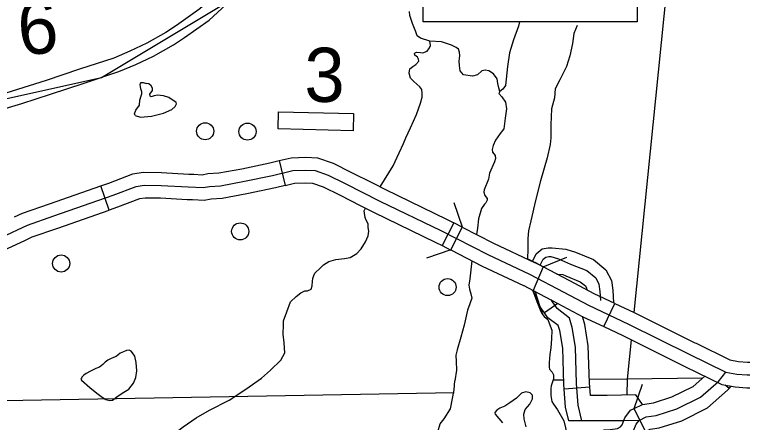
# Model space of a CAD drawing. Extents: x 22866 to 28196, y 1324810 to 1328105.
# Drawn here: x 25255.5 to 25357.6, y 1326025 to 1326082.2 of the extents above; entities that cross this region are included whole.
import ezdxf

# ---------------------------------------------------------------- set-up
doc = ezdxf.new("R2010")
doc.units = 0
for name, color, linetype in [('Default', 7, 'Continuous'), ('Level 19', 7, 'Continuous'), ('Level 31', 7, 'Continuous'), ('Level 32', 7, 'Continuous'), ('Level 35', 7, 'Continuous'), ('Level 38', 7, 'Continuous'), ('Level 4', 7, 'Continuous'), ('Level 46', 7, 'Continuous'), ('Level 5', 7, 'Continuous'), ('Level 56', 7, 'Continuous'), ('Level 9', 7, 'Continuous')]:
    doc.layers.add(name, color=color, linetype=linetype)

msp = doc.modelspace()

# ---------------------------------------------------------------- linework, layer by layer
at = {"layer": 'Default'}
for p, q in [((25267.72, 1326073.42), (25286.19, 1326084.53)), ((25247.38, 1326068.88), (25267.72, 1326073.42))]:
    msp.add_line(p, q, dxfattribs=at)
msp.add_lwpolyline([(25312.85, 1326111.22), (25342.85, 1326111.22), (25342.85, 1326081.22), (25312.85, 1326081.22)], close=True, dxfattribs=at)
msp.add_lwpolyline([(25312.85, 1326111.22), (25342.85, 1326111.22), (25342.85, 1326081.22), (25312.85, 1326081.22)], close=True, dxfattribs=at)
at = {"layer": 'Level 19'}
for points in [[(25294.2, 1326097.43), (25292, 1326094.49), (25288.16, 1326089.69), (25287.08, 1326088.34), (25285.72, 1326086.86), (25283.85, 1326085.15), (25281.53, 1326083.06), (25278.23, 1326080.71), (25276.73, 1326079.74), (25274.1, 1326078.22), (25271.69, 1326077.1), (25269.43, 1326076.14), (25264.65, 1326074.56), (25259.94, 1326073), (25255.94, 1326071.72), (25252.61, 1326070.71), (25248.87, 1326069.47), (25245.88, 1326068.29), (25242.81, 1326066.99), (25239.52, 1326065.45), (25236.93, 1326064.23)], [(25237.8, 1326062.38), (25240.39, 1326063.6), (25243.64, 1326065.12), (25246.65, 1326066.4), (25249.57, 1326067.55), (25253.23, 1326068.77), (25256.54, 1326069.77), (25260.58, 1326071.06), (25265.29, 1326072.62), (25270.15, 1326074.23), (25272.53, 1326075.24), (25275.04, 1326076.41), (25277.8, 1326078), (25279.37, 1326079.02), (25282.81, 1326081.46), (25285.22, 1326083.64), (25287.16, 1326085.42), (25288.63, 1326087.01), (25289.75, 1326088.42), (25293.61, 1326093.24), (25295.83, 1326096.2)]]:
    msp.add_lwpolyline(points, dxfattribs=at)
at = {"layer": 'Level 31'}
for p, q in [((25292.63, 1326061.74), (25293.47, 1326058.24)), ((25268.81, 1326054.79), (25267.62, 1326058.19)), ((25317.13, 1326053.02), (25315.49, 1326049.81)), ((25338.2, 1326038.44), (25339.74, 1326041.69))]:
    msp.add_line(p, q, dxfattribs=at)
for points in [[(25292.63, 1326061.74), (25294.31, 1326062.14), (25296.39, 1326062.22), (25298.03, 1326062.14), (25300.23, 1326061.36), (25302.71, 1326060.14), (25305.74, 1326058.6)], [(25280.67, 1326059.82), (25281.85, 1326059.76), (25282.64, 1326059.91), (25284.19, 1326060.01), (25287.43, 1326060.61), (25291.32, 1326061.42), (25292.63, 1326061.74)], [(25267.62, 1326058.19), (25268.73, 1326058.58), (25272.14, 1326059.87), (25273.57, 1326060.1), (25276.13, 1326060.06), (25279.95, 1326059.85), (25280.67, 1326059.82)], [(25255.53, 1326053.85), (25256.64, 1326054.37), (25260.43, 1326055.67), (25267.62, 1326058.19)], [(25293.47, 1326058.24), (25292.11, 1326057.91), (25288.12, 1326057.08), (25284.64, 1326056.43), (25283.1, 1326056.33), (25282.11, 1326056.14), (25280.49, 1326056.22)], [(25293.47, 1326058.24), (25294.81, 1326058.56), (25296.36, 1326058.62), (25297.33, 1326058.57), (25298.83, 1326058.04), (25301.09, 1326056.92), (25304.11, 1326055.39)], [(25305.74, 1326058.6), (25307.54, 1326057.68), (25316.11, 1326053.53), (25317.13, 1326053.02)], [(25280.49, 1326056.22), (25279.76, 1326056.25), (25276, 1326056.46), (25273.83, 1326056.49), (25273.07, 1326056.37), (25269.96, 1326055.2), (25268.81, 1326054.79)], [(25257.05, 1326050.59), (25257.99, 1326051.03), (25261.61, 1326052.27), (25268.81, 1326054.79)], [(25304.11, 1326055.39), (25305.95, 1326054.46), (25314.51, 1326050.31), (25315.49, 1326049.81)], [(25316.7, 1326049.19), (25318.33, 1326052.4), (25317.13, 1326053.02)], [(25318.33, 1326052.4), (25322.71, 1326050.16), (25328.45, 1326047.46)], [(25245.73, 1326044.96), (25250.87, 1326047.46), (25254.52, 1326049.41), (25257.05, 1326050.59)], [(25315.49, 1326049.81), (25316.7, 1326049.19)], [(25316.72, 1326049.23), (25321.12, 1326046.93), (25326.92, 1326044.2)], [(25329.66, 1326046.83), (25328.54, 1326047.42), (25329.66, 1326046.83), (25328.27, 1326043.53)], [(25339.74, 1326041.69), (25336.84, 1326043.06), (25333.4, 1326044.87), (25329.66, 1326046.83)], [(25326.92, 1326044.2), (25326.94, 1326044.2), (25328.27, 1326043.53)], [(25328.27, 1326043.53), (25331.72, 1326041.68), (25335.24, 1326039.84), (25338.2, 1326038.44)], [(25339.74, 1326041.69), (25342.43, 1326040.42), (25350.94, 1326036.19), (25351.14, 1326036.1)], [(25338.2, 1326038.44), (25340.86, 1326037.18), (25349.34, 1326032.96), (25349.55, 1326032.86)], [(25351.14, 1326036.1), (25355.87, 1326033.78), (25357.07, 1326033.56), (25358.35, 1326033.46), (25361.51, 1326033.46), (25362.41, 1326033.47)], [(25349.55, 1326032.86), (25354.73, 1326030.32), (25356.62, 1326029.98), (25358.22, 1326029.86), (25361.52, 1326029.86), (25362.44, 1326029.87)]]:
    msp.add_lwpolyline(points, dxfattribs=at)
at = {"layer": 'Level 32'}
for p, q in [((25330.85, 1326046.24), (25327.64, 1326047.86)), ((25331.71, 1326041.69), (25329.85, 1326040.37)), ((25355.76, 1326029.77), (25355.18, 1326030.24)), ((25336.21, 1326029.94), (25332.62, 1326029.65)), ((25344.04, 1326023.73), (25342.46, 1326026.96))]:
    msp.add_line(p, q, dxfattribs=at)
for points in [[(25328.17, 1326047.59), (25328.71, 1326048.66), (25329.54, 1326049.34), (25330.38, 1326049.48), (25330.93, 1326049.48), (25332.85, 1326049.32)], [(25332.85, 1326049.32), (25334.22, 1326048.89), (25336.74, 1326047.88), (25338.48, 1326046.43), (25339.24, 1326044.92), (25339.43, 1326043.58), (25339.55, 1326041.78)], [(25329.25, 1326047.05), (25329.67, 1326047.89), (25330.06, 1326048.21), (25330.48, 1326048.28), (25330.76, 1326048.28), (25331.81, 1326047.96), (25333.53, 1326047.22), (25335.81, 1326046.31), (25337.04, 1326045.29), (25337.5, 1326044.38), (25337.64, 1326043.39), (25337.72, 1326042.11)], [(25331.61, 1326045.81), (25332.41, 1326045.75)], [(25332.41, 1326045.75), (25332.84, 1326045.56), (25334.88, 1326044.74), (25335.6, 1326044.15), (25335.76, 1326043.83), (25335.79, 1326043.62)], [(25329.85, 1326040.37), (25329.24, 1326041.24), (25328.54, 1326043.4)], [(25333.37, 1326039.65), (25331.64, 1326040.97), (25330.87, 1326042.05), (25330.8, 1326042.27)], [(25332.62, 1326029.65), (25332.56, 1326030.35), (25332.41, 1326035.4), (25331.99, 1326037.92), (25331.8, 1326038.58), (25330.33, 1326039.7), (25329.85, 1326040.37)], [(25335.1, 1326025.2), (25334.6, 1326027.43), (25334.36, 1326030.45), (25334.21, 1326035.58), (25333.75, 1326038.32), (25333.37, 1326039.65)], [(25336.21, 1326029.94), (25336.16, 1326030.55), (25336, 1326035.76), (25335.51, 1326038.72), (25335.18, 1326039.87)], [(25339.25, 1326022.19), (25340.73, 1326022.43), (25341.71, 1326023), (25342.31, 1326023.73), (25342.73, 1326024.75), (25343.12, 1326025.28), (25344.14, 1326025.77), (25345.54, 1326025.98), (25348.42, 1326026.9), (25351.72, 1326028.55), (25354.25, 1326030.76), (25355.3, 1326032.05)], [(25342.46, 1326026.96), (25343.6, 1326027.51), (25345.13, 1326027.74), (25347.74, 1326028.57), (25350.71, 1326030.05), (25352.35, 1326031.49)], [(25333.26, 1326025.2), (25332.82, 1326027.15), (25332.62, 1326029.65)], [(25336.3, 1326028.8), (25336.21, 1326029.94)], [(25344.04, 1326023.73), (25344.67, 1326024.03), (25345.95, 1326024.22), (25349.1, 1326025.22), (25352.73, 1326027.04), (25355.55, 1326029.51), (25355.76, 1326029.77)], [(25355.76, 1326029.77), (25356.02, 1326030.09)], [(25343.6, 1326027.51), (25342.66, 1326028.87), (25338.64, 1326028.8), (25336.3, 1326028.8)], [(25332.16, 1326018.98), (25332.71, 1326019.84), (25333.83, 1326021.19), (25334.03, 1326021.32), (25335.78, 1326022.76), (25337.37, 1326023.49), (25338.23, 1326023.97), (25339.09, 1326023.99), (25340.12, 1326024.16), (25340.53, 1326024.39), (25340.75, 1326024.66), (25341.15, 1326025.64), (25341.93, 1326026.7), (25342.46, 1326026.96)], [(25340.97, 1326025.2), (25333.26, 1326025.2)], [(25343.12, 1326025.28), (25338.67, 1326025.2), (25335.1, 1326025.2)], [(25340.79, 1326025.24), (25338.67, 1326025.2), (25336.3, 1326025.2)]]:
    msp.add_lwpolyline(points, dxfattribs=at)
at = {"layer": 'Level 35'}
for points in [[(25323.6, 1326071.46), (25323.44, 1326071.96), (25323.33, 1326072.58), (25323.2, 1326073.24), (25322.71, 1326073.92), (25322.03, 1326074.36), (25321.56, 1326074.44), (25321.06, 1326074.34), (25320.46, 1326073.79), (25319.75, 1326073.6), (25318.52, 1326073.76), (25318.05, 1326074.34), (25317.95, 1326075.07), (25317.87, 1326075.72), (25318, 1326076.46), (25317.95, 1326076.98), (25317.82, 1326077.4), (25317.45, 1326077.61), (25316.8, 1326077.95), (25315.39, 1326078.42), (25313.79, 1326078.5), (25312.49, 1326078.91), (25312.02, 1326079.23), (25311.83, 1326079.83), (25311.34, 1326080.98), (25310.97, 1326082.11), (25310.94, 1326082.66)], [(25311.06, 1326066.35), (25311.92, 1326068.21), (25312.47, 1326069.8), (25312.68, 1326070.64), (25312.71, 1326071.19), (25312.66, 1326071.71), (25312.37, 1326072.1), (25311.51, 1326072.86), (25311.06, 1326073.33), (25310.88, 1326074.01), (25310.93, 1326074.35), (25310.98, 1326074.64), (25311.37, 1326074.96), (25311.79, 1326075.24), (25312.24, 1326075.69), (25312.21, 1326075.98), (25312.05, 1326076.24), (25311.66, 1326076.53), (25311.61, 1326076.76), (25311.74, 1326076.89), (25311.92, 1326076.94), (25312.45, 1326076.92), (25312.81, 1326076.89), (25313.39, 1326077.08), (25313.75, 1326077.55), (25313.86, 1326077.91), (25313.79, 1326078.5)], [(25272.43, 1326068.05), (25272.35, 1326068.3), (25272.53, 1326068.8), (25273.03, 1326069.53), (25273.11, 1326070.21), (25273.29, 1326070.84), (25273.37, 1326071.13), (25273.37, 1326071.39), (25273.24, 1326071.83), (25273.18, 1326072.12), (25273.16, 1326072.41), (25273.18, 1326072.56), (25273.29, 1326072.72), (25273.55, 1326072.72), (25274.05, 1326072.56)], [(25272.43, 1326068.05), (25273.18, 1326067.86), (25274.75, 1326067.99), (25276.43, 1326068.38), (25277.6, 1326068.93), (25278.07, 1326069.35), (25278.23, 1326069.71), (25278.2, 1326069.9), (25277.18, 1326070.58), (25276.43, 1326070.81), (25275.98, 1326070.89), (25275.61, 1326070.94), (25275.12, 1326070.84), (25274.7, 1326070.68), (25274.54, 1326070.79), (25274.52, 1326071.07), (25274.86, 1326071.6), (25274.88, 1326071.91), (25274.67, 1326072.22), (25274.36, 1326072.51), (25274.05, 1326072.56)], [(25306.79, 1326058.07), (25308.62, 1326061.03), (25309.49, 1326062.82), (25310.07, 1326064.15), (25310.42, 1326064.93), (25311.06, 1326066.35)], [(25293.43, 1326034.78), (25293.36, 1326036.18), (25293.2, 1326037.39), (25293.23, 1326038.69), (25293.25, 1326039.24), (25293.7, 1326040.5), (25294.22, 1326041.91), (25295.01, 1326042.67), (25295.66, 1326043.17), (25296.23, 1326043.46), (25296.63, 1326043.46), (25297.15, 1326043.72), (25297.28, 1326044.16), (25297.33, 1326044.84), (25297.36, 1326045.18), (25297.49, 1326045.63), (25297.65, 1326045.94), (25298.43, 1326046.71), (25298.87, 1326047.13), (25299.61, 1326047.57), (25300.57, 1326047.86), (25301.8, 1326047.99), (25302.59, 1326048.15), (25303.53, 1326048.72), (25304.15, 1326049.35), (25304.75, 1326050.32), (25305.12, 1326051.18), (25305.23, 1326051.86), (25305.15, 1326052.36), (25305.15, 1326052.88), (25304.8, 1326053.46), (25304.7, 1326053.75), (25304.59, 1326054.37), (25304.57, 1326054.69), (25304.74, 1326055.07)], [(25271.62, 1326035.13), (25271.25, 1326035.08), (25270.83, 1326034.89), (25270.32, 1326034.7), (25270, 1326034.44), (25269.79, 1326034.26), (25269.4, 1326034.11), (25269, 1326033.92), (25268.61, 1326033.75), (25268.26, 1326033.44), (25267.91, 1326033.13), (25267.45, 1326032.76), (25266.91, 1326032.55), (25266.19, 1326032.21), (25265.58, 1326031.87), (25265.25, 1326031.62), (25264.95, 1326031.35), (25264.9, 1326031.19), (25264.84, 1326031.07), (25264.93, 1326030.92)], [(25264.93, 1326030.92), (25266.09, 1326029.92), (25267.08, 1326029.11), (25267.8, 1326028.56), (25268.34, 1326028.2), (25268.9, 1326028.06), (25269.25, 1326028.12), (25269.87, 1326028.57), (25270.64, 1326029.1), (25271.54, 1326029.66), (25272.22, 1326030.52), (25272.56, 1326031.3), (25272.7, 1326032.25), (25272.57, 1326033.41), (25272.38, 1326034.28), (25272.09, 1326034.76), (25271.88, 1326035.02), (25271.62, 1326035.13)], [(25281, 1326025.66), (25282.89, 1326026.72), (25285.64, 1326028.13), (25287.96, 1326029.65), (25290.16, 1326031.22), (25291.41, 1326032.35), (25292.88, 1326033.73), (25293.43, 1326034.78)], [(25247.49, 1326013.88), (25249.97, 1326014.88), (25251.8, 1326015.85), (25254, 1326016.48), (25257.58, 1326018.42), (25260.06, 1326019.44), (25262.54, 1326020.35), (25265.24, 1326021.19), (25267.12, 1326021.66), (25268.16, 1326021.82), (25270.39, 1326021.82), (25273.68, 1326022.05), (25276.24, 1326022.58), (25277.76, 1326023.31), (25279.17, 1326024.38), (25281, 1326025.66)]]:
    msp.add_lwpolyline(points, dxfattribs=at)
at = {"layer": 'Level 38'}
for points in [[(25317.15, 1326055.85), (25318.31, 1326052.44)], [(25316.72, 1326049.21), (25313.31, 1326048.05)], [(25329.66, 1326046.85), (25332.99, 1326048.21)], [(25329.63, 1326040.2), (25328.27, 1326043.53)], [(25342.45, 1326026.94), (25343.59, 1326030.36)]]:
    msp.add_lwpolyline(points, dxfattribs=at)
at = {"layer": 'Level 4'}
for points in [[(25347.34, 1326089.47), (25342.39, 1326040.43)], [(25342, 1326036.61), (25341.45, 1326031.08), (25341.4, 1326028.85)]]:
    msp.add_lwpolyline(points, dxfattribs=at)
at = {"layer": 'Level 46'}
for points in [[(25261.02, 1326053.97), (25269.35, 1326056.89), (25272.6, 1326058.12), (25273.7, 1326058.29), (25276.07, 1326058.26), (25279.86, 1326058.05), (25281.98, 1326057.95), (25282.87, 1326058.12), (25284.41, 1326058.22), (25287.77, 1326058.84), (25291.72, 1326059.67), (25294.56, 1326060.35), (25296.38, 1326060.42), (25297.68, 1326060.35), (25299.53, 1326059.7), (25301.9, 1326058.53)], [(25301.9, 1326058.53), (25306.75, 1326056.07), (25315.31, 1326051.92), (25321.91, 1326048.55), (25327.74, 1326045.81), (25332.56, 1326043.28)], [(25235.19, 1326043.23), (25237.79, 1326043.41), (25238.58, 1326043.58), (25240.45, 1326044.19), (25244.84, 1326046.53), (25250.05, 1326049.07), (25253.72, 1326051.02), (25257.32, 1326052.7), (25261.02, 1326053.97)], [(25332.56, 1326043.28), (25336.04, 1326041.45)], [(25336.04, 1326041.45), (25341.64, 1326038.8), (25350.14, 1326034.58), (25355.3, 1326032.05), (25356.85, 1326031.77), (25358.28, 1326031.66), (25361.51, 1326031.66), (25368.39, 1326031.73), (25395.12, 1326032.05), (25413.76, 1326032.22), (25425.96, 1326032.47), (25436.24, 1326032.61), (25440.81, 1326032.65), (25446.74, 1326032.75), (25455.79, 1326032.8)]]:
    msp.add_lwpolyline(points, dxfattribs=at)
at = {"layer": 'Level 5'}
for points in [[(25352.04, 1326031.22), (25341.45, 1326031.08)], [(25332.54, 1326030.95), (25331.14, 1326030.93)], [(25341.45, 1326031.08), (25336.14, 1326031)], [(25317.18, 1326029.15), (25240.82, 1326027.81)]]:
    msp.add_lwpolyline(points, dxfattribs=at)
at = {"layer": 'Level 56'}
msp.add_lwpolyline([(25292.5, 1326066.19), (25292.56, 1326068.58), (25303.06, 1326068.33), (25303, 1326065.93)], close=True, dxfattribs=at)
for centre in [(25282.27, 1326065.86), (25288.2, 1326065.81), (25287.18, 1326051.81), (25262.06, 1326047.3), (25316.27, 1326043.99)]:
    msp.add_circle(centre, 1.2, dxfattribs=at)
at = {"layer": 'Level 9'}
for points in [[(25326.35, 1326081.22), (25326.19, 1326080.59), (25325.51, 1326078.71), (25324.96, 1326076.87), (25324.67, 1326074.94), (25324.41, 1326072.27), (25324.02, 1326071.75), (25323.6, 1326071.46), (25323.47, 1326071.17)], [(25334.45, 1326080.68), (25333.96, 1326079.56), (25333.77, 1326078.2), (25333.43, 1326076.44), (25332.96, 1326074.95), (25332.02, 1326073.07), (25331.34, 1326071.83), (25331.24, 1326070.57), (25330.85, 1326069.03), (25330.74, 1326066.75), (25330.74, 1326064.95), (25330.66, 1326063.98), (25330.22, 1326062.15), (25329.28, 1326058.89), (25328.6, 1326056.14), (25327.94, 1326053.27), (25327.6, 1326051.88), (25327.53, 1326050.81), (25327.53, 1326049.41), (25327.48, 1326047.92)], [(25323.47, 1326071.17), (25323.89, 1326070.69), (25324.41, 1326069.96), (25324.52, 1326068.99), (25324.36, 1326067.69), (25324.15, 1326066.19), (25323.66, 1326065.54), (25323, 1326064.6), (25322.66, 1326063.84), (25322.51, 1326063.32), (25322.56, 1326062.92), (25322.92, 1326062.48), (25322.98, 1326062.03), (25322.85, 1326061.56), (25322.14, 1326059.97), (25322.01, 1326059.16), (25321.38, 1326057.66), (25321.33, 1326057.32), (25321.51, 1326056.85), (25321.8, 1326056.44), (25321.83, 1326056.17), (25321.64, 1326055.81), (25321.43, 1326055.62)], [(25321.43, 1326055.62), (25321.02, 1326055.04), (25320.6, 1326053.57), (25320.47, 1326052.24), (25320.34, 1326051.37)], [(25319.67, 1326047.69), (25319.39, 1326045.17), (25319.24, 1326044.26)], [(25319.24, 1326044.26), (25319.32, 1326043.69), (25319.55, 1326043.04), (25319.68, 1326042.44), (25319.37, 1326041.63), (25319.06, 1326040.74), (25318.58, 1326038.64), (25318.11, 1326036.97), (25317.62, 1326035.19), (25317.43, 1326034.46), (25317.46, 1326033.57), (25317.54, 1326032.34), (25317.28, 1326030.85)], [(25328.17, 1326043.58), (25328.47, 1326042.87), (25328.79, 1326041.99), (25329.25, 1326040.81), (25329.49, 1326040.3)], [(25329.49, 1326040.3), (25329.8, 1326039.88), (25330.35, 1326039.46), (25330.66, 1326038.57), (25330.9, 1326037.94), (25330.84, 1326036.74), (25330.74, 1326035.46), (25330.63, 1326034.54), (25330.53, 1326033.42), (25330.5, 1326032.74), (25330.58, 1326032.45), (25330.95, 1326032.06), (25331.1, 1326031.66), (25331.13, 1326031.11), (25330.79, 1326030.12), (25330.74, 1326029.78), (25330.74, 1326028.76), (25330.87, 1326027.92), (25331.1, 1326027.58), (25331.68, 1326026.77), (25332.57, 1326025.23)], [(25313.09, 1326018.65), (25313.96, 1326020.93), (25314.59, 1326022.55), (25315.22, 1326024.8), (25315.77, 1326025.51), (25316.68, 1326026.92), (25317.2, 1326029.59), (25317.28, 1326030.85)], [(25327.29, 1326024.4), (25327.01, 1326025.52), (25326.95, 1326026.15), (25327.16, 1326026.83), (25327.79, 1326027.56), (25328.16, 1326028.3), (25328.18, 1326028.82), (25327.84, 1326029.16), (25327.24, 1326029.27), (25326.64, 1326029.11), (25325.93, 1326028.4), (25324.99, 1326027.77), (25324.29, 1326027.3), (25323.58, 1326027.01), (25323.16, 1326026.7), (25322.9, 1326026.41), (25322.95, 1326026.13)], [(25322.95, 1326026.15), (25323.95, 1326024.95)], [(25332.57, 1326025.23), (25333.02, 1326023.25), (25333.42, 1326022.17), (25333.51, 1326021.36), (25333.38, 1326020.87), (25332.7, 1326019.98), (25331.64, 1326018.92), (25331.16, 1326018.22), (25330.82, 1326016.96), (25330.54, 1326015.79), (25330.48, 1326014.31), (25330.48, 1326013.25)]]:
    msp.add_lwpolyline(points, dxfattribs=at)

# ---------------------------------------------------------------- texts
at = {"layer": 'Level 56'}
msp.add_text('6', height=7.6, rotation=4.579, dxfattribs=at).set_placement((25256.25, 1326076.51))
msp.add_text('3', height=7.6, dxfattribs=at).set_placement((25296.18, 1326069.98))

doc.saveas('drawing.dxf')
